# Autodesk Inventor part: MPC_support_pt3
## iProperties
Shininess: 64.0
Length Units: 11272
Angle Units: 11279
Time Units: 11290
Mass Units: 11286
Length Display Precision: 3
Angle Display Precision: 2
Compacted: True
Part Number: MPC_support_pt3
Document SubType Name: Modeling
Created: 2004-08
Designer: John Blackburn
Manufacturer: Standard
Standards Organization: Custom
Density: 0.0
Volumn: 0.0
Area: 0.0
PropertySet Name: Model Information
Control State: 0
Master: False
Checked Out: False
Author: John Blackburn
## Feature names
1. Extrusion1
2. Extrusion2
3. Chamfer2
4. Base1
